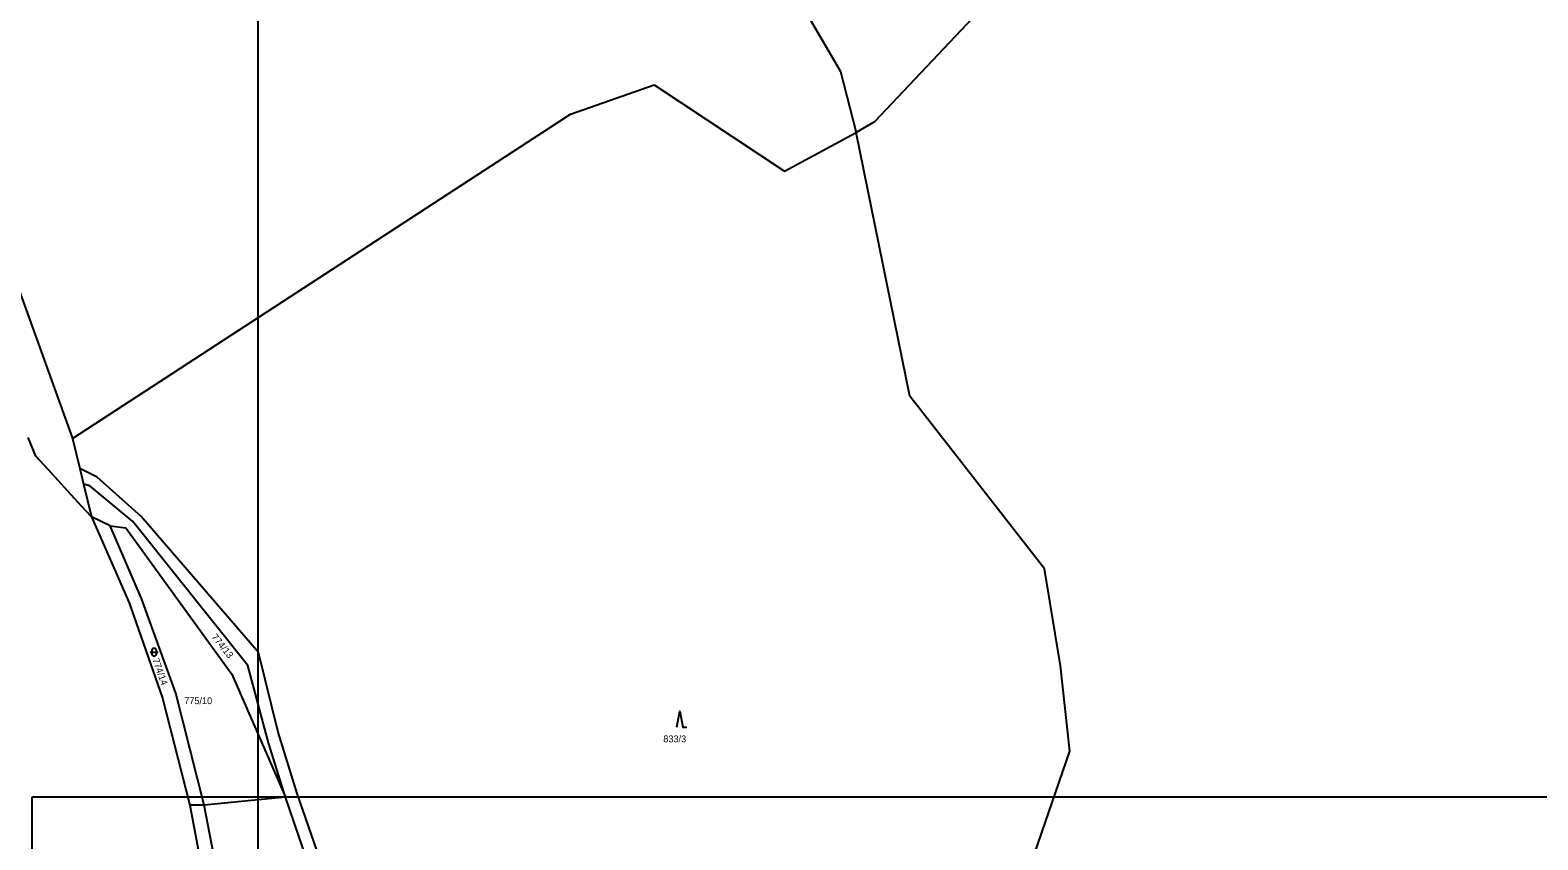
# Model space of a CAD drawing. Extents: x -801907 to -800293, y -1017000 to -1015684.
# Drawn here: x -801306.6 to -800931.6, y -1016334.3 to -1016132.8 of the extents above; entities that cross this region are included whole.
import ezdxf

# ---------------------------------------------------------------- set-up
doc = ezdxf.new("R2010")
doc.units = 0
for name, color, linetype in [('Default', 7, 'Continuous'), ('KLADY_ZMVM', 7, 'Continuous'), ('KN_HRANICE', 7, 'Continuous'), ('KN_KULTURY', 7, 'Continuous'), ('KN_PARCELY', 7, 'Continuous'), ('LEGENDA', 7, 'Continuous')]:
    doc.layers.add(name, color=color, linetype=linetype)

# ---------------------------------------------------------------- blocks, each defined once
blk = doc.blocks.new('308')
at = {"layer": 'Default'}
blk.add_lwpolyline([(-0.75, 0), (0, 4), (0.75, 0), (1.75, 0)], dxfattribs=at)
blk = doc.blocks.new('316')
at = {"layer": 'Default'}
for points in [[(-1, 1), (0.27, 1), (1, 1)], [(-0.5, 1.5), (-0.4, 1.79), (-0.15, 1.97), (0.16, 1.97), (0.41, 1.79), (0.51, 1.5), (0.51, 0.5), (0.41, 0.21), (0.16, 0.03), (-0.15, 0.03), (-0.4, 0.21), (-0.5, 0.5), (-0.5, 1.5)]]:
    blk.add_lwpolyline(points, dxfattribs=at)

msp = doc.modelspace()

# ---------------------------------------------------------------- linework, layer by layer
at = {"layer": 'KLADY_ZMVM'}
msp.add_lwpolyline([(-801250, -1016000), (-801250, -1016500), (-801250, -1017000)], dxfattribs=at)
at = {"layer": 'KN_HRANICE'}
for p, q in [((-801119.11, -1016118.95), (-801105.07, -1016143.14)), ((-801072.19, -1016129.88), (-801096.58, -1016155.67)), ((-801105.07, -1016143.14), (-801101.16, -1016158.27)), ((-801327.07, -1016148.63), (-801296.08, -1016234.39)), ((-801172.18, -1016153.77), (-801151.44, -1016146.42)), ((-801151.44, -1016146.42), (-801118.95, -1016167.92)), ((-801296.08, -1016234.39), (-801172.18, -1016153.77)), ((-801096.58, -1016155.67), (-801101.16, -1016158.27)), ((-801118.95, -1016167.92), (-801101.16, -1016158.27)), ((-801087.8, -1016223.87), (-801101.16, -1016158.27)), ((-801054.29, -1016266.88), (-801087.8, -1016223.87)), ((-801305.22, -1016238.85), (-801307.14, -1016234.16)), ((-801296.08, -1016234.39), (-801294.26, -1016241.91)), ((-801302.16, -1016242.17), (-801305.22, -1016238.85)), ((-801296.43, -1016248.4), (-801302.16, -1016242.17)), ((-801289.98, -1016244.05), (-801294.26, -1016241.91)), ((-801294.26, -1016241.91), (-801293.32, -1016245.8)), ((-801293.32, -1016245.8), (-801291.35, -1016253.92)), ((-801291.77, -1016246.21), (-801293.32, -1016245.8)), ((-801281.12, -1016255.04), (-801291.77, -1016246.21)), ((-801278.99, -1016253.83), (-801289.98, -1016244.05)), ((-801293.82, -1016251.23), (-801296.43, -1016248.4)), ((-801291.35, -1016253.92), (-801293.82, -1016251.23)), ((-801286.71, -1016256.11), (-801291.35, -1016253.92)), ((-801291.35, -1016253.92), (-801281.96, -1016275.28)), ((-801249.86, -1016287.66), (-801278.99, -1016253.83)), ((-801286.71, -1016256.11), (-801282.82, -1016256.61)), ((-801278.95, -1016274.23), (-801286.71, -1016256.11)), ((-801282.82, -1016256.61), (-801256.44, -1016293.08)), ((-801252.47, -1016290.85), (-801281.12, -1016255.04)), ((-801050.29, -1016291), (-801054.29, -1016266.88)), ((-801281.96, -1016275.28), (-801273.73, -1016298.99)), ((-801270.4, -1016297.77), (-801278.95, -1016274.23)), ((-801244.9, -1016307.46), (-801249.86, -1016287.66)), ((-801247.34, -1016310.15), (-801252.47, -1016290.85)), ((-801047.99, -1016312.24), (-801050.29, -1016291)), ((-801256.44, -1016293.08), (-801243.11, -1016323.66)), ((-801273.73, -1016298.99), (-801266.91, -1016325.63)), ((-801263.32, -1016325.64), (-801270.4, -1016297.77)), ((-801240.17, -1016322.77), (-801244.9, -1016307.46)), ((-801243.11, -1016323.66), (-801247.34, -1016310.15)), ((-801061.14, -1016350.27), (-801047.99, -1016312.24)), ((-801263.32, -1016325.64), (-801266.91, -1016325.63)), ((-801266.91, -1016325.63), (-801262.33, -1016349.67)), ((-801243.11, -1016323.66), (-801263.32, -1016325.64)), ((-801256.32, -1016362.14), (-801263.32, -1016325.64)), ((-801235.95, -1016344.57), (-801243.11, -1016323.66)), ((-801232.53, -1016344.87), (-801240.17, -1016322.77))]:
    msp.add_line(p, q, dxfattribs=at)
at = {"layer": 'LEGENDA'}
msp.add_lwpolyline([(-801306.12, -1016323.56), (-800712.12, -1016323.56), (-800712.12, -1016743.56), (-801306.12, -1016743.56)], close=True, dxfattribs=at)

# ---------------------------------------------------------------- block references
at = {"layer": 'KN_KULTURY'}
for name, p in [('316', (-801275.77, -1016288.57)), ('308', (-801145, -1016306.26))]:
    msp.add_blockref(name, p, dxfattribs=at)

# ---------------------------------------------------------------- texts
at = {"layer": 'KN_PARCELY'}
for s, rotation, p in [('774/13', 308.939, (-801261.63, -1016283.87)), ('774/14', 289.516, (-801276.25, -1016289.41))]:
    msp.add_text(s, height=1.7, rotation=rotation, dxfattribs=at).set_placement(p)
for s, p in [('775/10', (-801268.3, -1016300.5)), ('833/3', (-801149.13, -1016310))]:
    msp.add_text(s, height=1.7, dxfattribs=at).set_placement(p)

doc.saveas('drawing.dxf')
